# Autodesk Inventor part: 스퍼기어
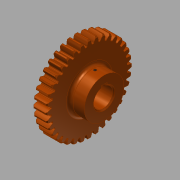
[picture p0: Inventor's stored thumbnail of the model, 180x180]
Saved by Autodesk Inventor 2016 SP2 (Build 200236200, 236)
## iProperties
Created: 2019-01
Part Number: 스퍼기어
Material: 알루미늄 6061
Document SubType Name: Modeling
Designer: mduedu
Density: 1 g/cm^3
Appearance: 매끄러움 - 연한 주황색
Author: mduedu
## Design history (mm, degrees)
sketch "스케치1"
  geometry: C1 r 33.5 at (0, 0); 1 further point
  constraints: 1 centre point, 1 coincident
  dimensions: "d0" = 67 diameter of C1
extrude "돌출1" new body sketch "스케치1" stored distance "d2" = 12; taper "d3" = 0 deg
sketch "스케치2" dims "d4" = 72
  geometry: L1 (0, 0)-(-38, 0); L2 (0, 0)-(0, 38); L3 (-0.57, 0)-(-0.57, 37.996); L4 (-1.57, 0)-(-1.57, 37.968); L5 (-2.07, 0)-(-2.07, 37.944); C1 r 33.5 at (0, 0); A1 r 38 centre (0, 0) between (-38, 0) and (0, 38); A2 r 9.246 centre (7.162, 32.926) between (-0.57, 37.996) and (-2.07, 33.436); A3 r 9.246 centre (-7.162, 32.926) between (2.07, 33.436) and (0.57, 37.996); A4 r 33.5 centre (0, 0) between (2.07, 33.436) and (-2.07, 33.436); A5 r 38 centre (0, 0) between (0.57, 37.996) and (-0.57, 37.996); 3 further points
  constraints: 14 point on circle, 10 end point, 6 centre point, 5 coincident, 5 point on line, 3 symmetric about line, 2 parallel, 2 perpendicular, 1 horizontal, 7 other
  dimensions: "d6" = 76 diameter of A1; "d7" = 0.5 distance between parallel lines of L4 L5; "d8" = 1 distance between parallel lines of L3 L4; "d9" = 1.57 distance between parallel lines of L2 L4
extrude "돌출2" join sketch "스케치2" stored distance "d10" = 0; taper "d11" = 0 deg
chamfer "모따기1" distance "d12" = 1; stored, may be unused: second distance "d13" = 2, angle "d14" = 45 deg
fillet "모깎기1" dims "d15" = 0.5
sketch "스케치3"
  geometry: C1 r 17.5 at (0, 0); 1 further point
  constraints: 1 centre point, 1 coincident
  dimensions: "d19" = 35 diameter of C1
extrude "돌출3" join sketch "스케치3" distance "d20" = 13; taper "d21" = 0 deg
sketch "스케치4"
  geometry: L1 (-2.5, 8.124)-(2.5, 8.124); L2 (2.5, 8.124)-(2.5, 10.8); L3 (2.5, 10.8)-(-2.5, 10.8); L4 (-2.5, 10.8)-(-2.5, 8.124); A1 r 8.5 centre (0, 0) between (-2.5, 8.124) and (2.5, 8.124); 1 further point
  constraints: 8 end point, 2 parallel, 2 point on circle, 1 centre point, 1 coincident, 1 horizontal, 1 perpendicular
  dimensions: "d22" = 17 diameter of A1; "d23" = 5 distance of L2.end L3.end; "d24" = 19.3 dimension on A1 L3
extrude "돌출4" cut sketch "스케치4" stored distance "d25" = 13; taper "d26" = 0 deg
sketch "스케치5"
  geometry: C1 r 15 at (0, 0); C2 r 27.5 at (0, 0); 1 further point
  constraints: 2 centre point, 2 coincident
  dimensions: "d33" = 30 diameter of C1; "d34" = 55 diameter of C2
extrude "돌출5" cut sketch "스케치5" distance "d30" = 6; taper "d31" = 0 deg
fillet "모깎기2" dims "d32" = 3
node "작업 평면1"
sketch "스케치6"
  geometry: L1 (17.5, 13)-(-17.5, 13) reference; 2 further points
  constraints: 1 vertical alignment
  dimensions: "d35" = 8 distance from line of point (0, 5) L1
hole "구멍1" sketch "스케치6" at (0, 5) diameter "d36" = 2.459; stored, may be unused: countersink angle "d40" = 90 deg, drill point angle "d42" = 118 deg; dims "d37" = 6, "d38" = 4, "d39" = 2, "d41" = 8
fillet "모깎기3" dims "d43" = 3
chamfer "모따기2" distance "d44" = 1; stored, may be unused: second distance "d45" = 2, angle "d46" = 45 deg
node "솔리드1"
pattern_circular "원형 패턴1" dims "d17" = 360 deg
